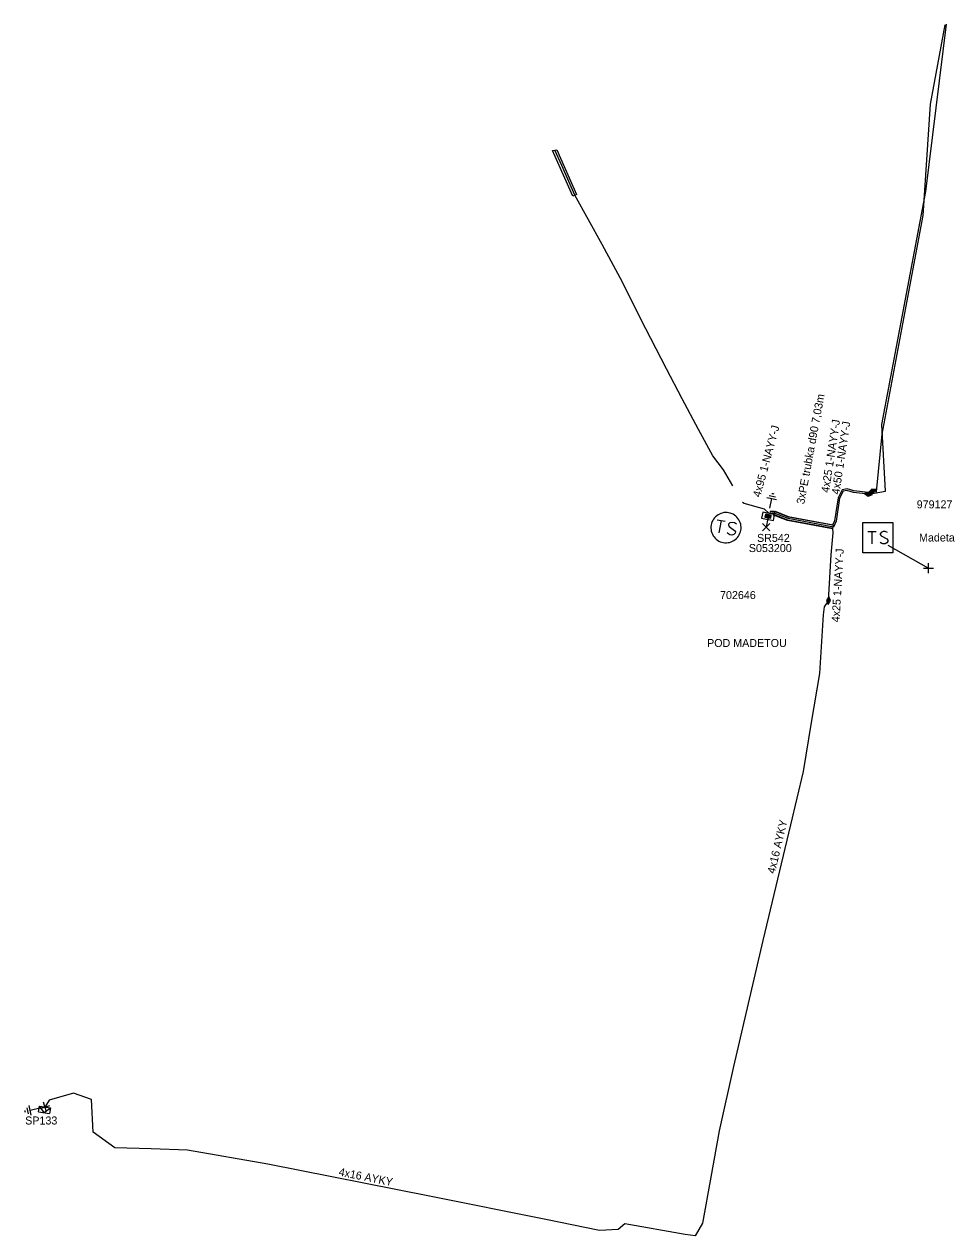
# Model space of a CAD drawing. Extents: x -737417 to -734469, y -1145580 to -1142703.
# Drawn here: x -734991.9 to -734875.7, y -1142926.1 to -1142774.8 of the extents above; entities that cross this region are included whole.
import ezdxf

# ---------------------------------------------------------------- set-up
doc = ezdxf.new("R2010")
doc.units = 0
for name, color, linetype in [('Vrstva 1', 7, 'Continuous'), ('Vrstva 14', 7, 'Continuous'), ('Vrstva 15', 7, 'Continuous'), ('Vrstva 19', 7, 'Continuous'), ('Vrstva 20', 7, 'Continuous'), ('Vrstva 21', 7, 'Continuous'), ('Vrstva 25', 7, 'Continuous'), ('Vrstva 26', 7, 'Continuous'), ('Vrstva 27', 7, 'Continuous'), ('Vrstva 28', 7, 'Continuous'), ('Vrstva 29', 7, 'Continuous'), ('Vrstva 30', 7, 'Continuous'), ('Vrstva 31', 7, 'Continuous'), ('Vrstva 33', 7, 'Continuous'), ('Vrstva 34', 7, 'Continuous'), ('Vrstva 4', 7, 'Continuous'), ('Vrstva 5', 7, 'Continuous'), ('Vrstva 52', 7, 'Continuous'), ('Vrstva 54', 7, 'Continuous'), ('Vrstva 59', 7, 'Continuous'), ('Vrstva 6', 7, 'Continuous'), ('Vrstva 8', 7, 'Continuous'), ('Vrstva 9', 7, 'Continuous')]:
    doc.layers.add(name, color=color, linetype=linetype)

# ---------------------------------------------------------------- blocks, each defined once
blk = doc.blocks.new('NN870')
at = {"layer": 'Vrstva 4'}
for points in [[(0, -0.25), (0.5, 0), (0, 0.25), (-0.5, 0), (0, -0.25)], [(0.37, 0), (0, 0.19), (-0.36, 0), (0, -0.19), (0.37, 0)], [(0.24, 0), (0, 0.12), (-0.25, 0), (0, -0.12), (0.24, 0)], [(0.12, 0), (0, 0.06), (-0.13, 0), (0, -0.06), (0.12, 0)]]:
    blk.add_lwpolyline(points, dxfattribs=at)
blk = doc.blocks.new('NN800')
at = {"layer": 'Vrstva 1'}
for points in [[(-0.44, 0.44), (0.44, -0.44)], [(-0.44, -0.44), (0.44, 0.44)]]:
    blk.add_lwpolyline(points, dxfattribs=at)
blk = doc.blocks.new('NN620')
at = {"layer": 'Vrstva 8'}
for points in [[(0.75, 0), (-0.75, 0)], [(-0.75, 0), (-0.75, -0.75)], [(0.75, -0.75), (0.75, 0)], [(-0.75, -0.75), (0.75, -0.75)], [(0.37, -0.18), (-0.38, -0.18)], [(-0.38, -0.18), (-0.38, -0.56)], [(-0.38, -0.56), (0.37, -0.56)], [(0.32, -0.23), (-0.33, -0.23)], [(-0.33, -0.23), (-0.33, -0.51)], [(-0.33, -0.51), (0.32, -0.51)], [(0.27, -0.27), (-0.28, -0.27)], [(-0.28, -0.27), (-0.28, -0.46)], [(-0.28, -0.46), (0.27, -0.46)], [(0.23, -0.32), (-0.23, -0.32)], [(-0.23, -0.32), (-0.23, -0.42)], [(-0.23, -0.42), (0.23, -0.42)], [(-0.19, -0.37), (0.19, -0.37)], [(0.23, -0.42), (0.23, -0.32)], [(0.27, -0.46), (0.27, -0.27)], [(0.32, -0.51), (0.32, -0.23)], [(0.37, -0.56), (0.37, -0.18)]]:
    blk.add_lwpolyline(points, dxfattribs=at)
blk = doc.blocks.new('NN630')
at = {"layer": 'Vrstva 9'}
for points in [[(0, -0.7), (-0.7, 0)], [(-0.7, -0.7), (-0.7, 0), (0.7, 0), (0.7, -0.7)], [(-0.7, -0.7), (0.7, -0.7)], [(0, -0.7), (0.7, 0)]]:
    blk.add_lwpolyline(points, dxfattribs=at)
blk = doc.blocks.new('NN810')
at = {"layer": 'Vrstva 14'}
for points in [[(0, -0.64), (0, -1.89)], [(0.63, -1.89), (-0.62, -1.89)], [(0.39, -2.2), (-0.4, -2.2)], [(0, -2.52), (-0.12, -2.52)], [(0.14, -2.52), (0, -2.52)]]:
    blk.add_lwpolyline(points, dxfattribs=at)
blk = doc.blocks.new('NN640')
at = {"layer": 'Vrstva 6'}
for points in [[(-1.89, 1.89), (1.89, 1.89)], [(-1.89, -1.89), (-1.89, 1.89)], [(1.89, 1.89), (1.89, -1.89)], [(-1.26, 0.79), (-0.22, 0.79)], [(-0.73, 0.79), (-0.73, -0.79)], [(1.2, 0.66), (0.94, 0.79), (0.66, 0.79), (0.41, 0.66), (0.28, 0.47), (0.28, 0.41), (0.41, 0.22), (1.13, -0.16), (1.26, -0.32), (1.26, -0.47), (1.13, -0.66), (0.91, -0.79), (0.63, -0.79), (0.5, -0.73), (0.28, -0.6)], [(1.89, -1.89), (-1.89, -1.89)]]:
    blk.add_lwpolyline(points, dxfattribs=at)
blk = doc.blocks.new('NN610')
at = {"layer": 'Vrstva 6'}
for points in [[(1.88, 0), (1.87, 0.2), (1.84, 0.39), (1.79, 0.58), (1.72, 0.77), (1.63, 0.94), (1.52, 1.11), (1.4, 1.26), (1.26, 1.4), (1.1, 1.53), (0.94, 1.63), (0.76, 1.72), (0.58, 1.8), (0.19, 1.88), (0.19, 1.88), (-0.01, 1.89), (-0.21, 1.88), (-0.4, 1.85), (-0.59, 1.8), (-0.78, 1.72), (-0.95, 1.63), (-1.12, 1.53), (-1.27, 1.4), (-1.41, 1.26), (-1.54, 1.11), (-1.64, 0.94), (-1.73, 0.77), (-1.8, 0.58), (-1.86, 0.39), (-1.89, 0.2), (-1.9, 0), (-1.89, -0.2), (-1.86, -0.39), (-1.8, -0.58), (-1.73, -0.77), (-1.64, -0.95), (-1.54, -1.11), (-1.41, -1.27), (-1.27, -1.41), (-1.12, -1.53), (-0.95, -1.64), (-0.78, -1.73), (-0.59, -1.8), (-0.4, -1.85), (-0.21, -1.88), (-0.01, -1.89), (0.19, -1.88), (0.39, -1.85), (0.58, -1.8), (0.76, -1.73), (0.94, -1.64), (1.1, -1.53), (1.26, -1.41), (1.4, -1.27), (1.52, -1.11), (1.63, -0.95), (1.72, -0.77), (1.79, -0.58), (1.84, -0.39), (1.87, -0.2), (1.88, 0)], [(-1.27, 0.78), (-0.26, 0.78)], [(-0.76, 0.78), (-0.76, -0.79)], [(1.19, 0.66), (0.94, 0.78), (0.62, 0.78), (0.37, 0.66), (0.24, 0.47), (0.24, 0.4), (0.37, 0.22), (1.12, -0.16), (1.25, -0.32), (1.25, -0.48), (1.12, -0.67), (0.87, -0.79), (0.62, -0.79), (0.49, -0.73), (0.24, -0.6)]]:
    blk.add_lwpolyline(points, dxfattribs=at)

msp = doc.modelspace()

# ---------------------------------------------------------------- linework, layer by layer
at = {"layer": 'Vrstva 20'}
for points in [[(-734925.42, -1142790.46), (-734922.94, -1142796.01), (-734923.4, -1142796.22), (-734925.93, -1142790.54)], [(-734890.87, -1142837.3), (-734890.96, -1142837.79), (-734896.57, -1142836.75), (-734898.32, -1142836.07), (-734898.14, -1142835.6), (-734896.48, -1142836.26)]]:
    msp.add_lwpolyline(points, close=True, dxfattribs=at)
at = {"layer": 'Vrstva 5'}
for points in [[(-734886.46, -1142833.45), (-734884.32, -1142833.09), (-734884.8, -1142824.75), (-734879.31, -1142795.66), (-734876.72, -1142774.76)], [(-734903.41, -1142832.41), (-734904.56, -1142830.41), (-734905.89, -1142828.67), (-734907.69, -1142825.4), (-734909.73, -1142821.55), (-734911.68, -1142817.81), (-734914.95, -1142811.51), (-734917.19, -1142806.98), (-734919.72, -1142802.29), (-734923.17, -1142796.11), (-734924.76, -1142792.42), (-734925.65, -1142790.49)], [(-734885.96, -1142833.06), (-734886.48, -1142833.25), (-734888.29, -1142833.07), (-734889.14, -1142832.82), (-734889.77, -1142832.91), (-734890.27, -1142833.91), (-734890.71, -1142836.79), (-734890.94, -1142837.34), (-734896.45, -1142836.32), (-734898.2, -1142835.63), (-734898.74, -1142835.65), (-734898.78, -1142835.89)], [(-734898.93, -1142835.86), (-734899.47, -1142835.33), (-734901.99, -1142834.65), (-734902.21, -1142834.5)], [(-734886.46, -1142833.45), (-734888.33, -1142833.27), (-734889.16, -1142833.02), (-734889.63, -1142833.09), (-734890.07, -1142833.97), (-734890.51, -1142836.85), (-734890.82, -1142837.57), (-734896.5, -1142836.51), (-734898.23, -1142835.83), (-734898.58, -1142835.84), (-734898.59, -1142835.92)], [(-734891.46, -1142846.75), (-734891.12, -1142841.05), (-734890.88, -1142838.31), (-734890.91, -1142837.76), (-734896.56, -1142836.7), (-734898.21, -1142836.05)]]:
    msp.add_lwpolyline(points, dxfattribs=at)
at = {"layer": 'Vrstva 52'}
for points in [[(-734885.96, -1142833.06), (-734885.46, -1142833.19), (-734884.76, -1142825.99), (-734883.75, -1142820.63), (-734879.64, -1142798.64), (-734878.72, -1142784.76), (-734876.9, -1142774.85)], [(-734891.46, -1142846.75), (-734892.02, -1142847.54), (-734892.14, -1142848.56), (-734892.6, -1142855.86), (-734893.61, -1142861.99), (-734894.62, -1142868.11), (-734896.21, -1142874.79), (-734899.67, -1142889.21), (-734903.32, -1142904.98), (-734905.1, -1142913.02), (-734906.16, -1142918.78), (-734907.21, -1142924.54), (-734908.12, -1142926.11), (-734909.38, -1142925.96), (-734916.91, -1142924.6), (-734917.72, -1142925.33), (-734920.09, -1142925.46), (-734926.79, -1142924.08), (-734941.29, -1142921.17), (-734961.49, -1142917.17), (-734971.56, -1142915.41), (-734976.1, -1142915.27), (-734980.64, -1142915.13), (-734983.33, -1142913.17), (-734983.52, -1142909.07), (-734985.79, -1142908.28), (-734988.84, -1142909.15), (-734989.35, -1142910.03)]]:
    msp.add_lwpolyline(points, dxfattribs=at)
at = {"layer": 'Vrstva 59'}
for points in [[(-734899.06, -1142836.51), (-734899.25, -1142837.59)], [(-734884.05, -1142839.82), (-734878.95, -1142842.72)]]:
    msp.add_lwpolyline(points, dxfattribs=at)

# ---------------------------------------------------------------- block references
at = {"layer": 'Vrstva 15'}
for p, rotation in [((-734898.93, -1142835.86), 168.26819729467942), ((-734989.35, -1142910.03), -77.21482219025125)]:
    msp.add_blockref('NN810', p, dxfattribs=dict(at, rotation=rotation))
at = {"layer": 'Vrstva 19'}
for p, rotation in [((-734885.96, -1142833.06), 20.337544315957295), ((-734886.46, -1142833.45), -5.583288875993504), ((-734891.46, -1142846.75), 86.58640281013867)]:
    msp.add_blockref('NN870', p, dxfattribs=dict(at, rotation=rotation))
at = {"layer": 'Vrstva 25', "rotation": -10.143019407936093}
msp.add_blockref('NN610', (-734904.26, -1142837.65), dxfattribs=at)
at = {"layer": 'Vrstva 25'}
msp.add_blockref('NN640', (-734885.3, -1142838.9), dxfattribs=at)
at = {"layer": 'Vrstva 28', "rotation": -11.454138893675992}
msp.add_blockref('NN620', (-734898.93, -1142835.86), dxfattribs=at)
at = {"layer": 'Vrstva 31', "rotation": -9.135105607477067}
msp.add_blockref('NN630', (-734989.35, -1142910.03), dxfattribs=at)
at = {"layer": 'Vrstva 34'}
msp.add_blockref('NN800', (-734899.25, -1142837.59), dxfattribs=at)
for p, rotation in [((-734878.95, -1142842.72), 44.99999995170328), ((-734989.35, -1142910.03), 63.62788614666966)]:
    msp.add_blockref('NN800', p, dxfattribs=dict(at, rotation=rotation))

# ---------------------------------------------------------------- texts
at = {"layer": 'Vrstva 21'}
msp.add_text('3xPE trubka d90 7,03m', height=1, rotation=79.447, dxfattribs=at).set_placement((-734894.5, -1142834.78))
at = {"layer": 'Vrstva 26'}
for s, p in [('979127', (-734880.44, -1142835.24)), ('702646', (-734905.01, -1142846.57))]:
    msp.add_text(s, height=1, dxfattribs=at).set_placement(p)
at = {"layer": 'Vrstva 27'}
for s, p in [('Madeta', (-734880.15, -1142839.38)), ('POD MADETOU', (-734906.63, -1142852.56))]:
    msp.add_text(s, height=1, dxfattribs=at).set_placement(p)
at = {"layer": 'Vrstva 29'}
msp.add_text('S053200', height=1, dxfattribs=at).set_placement((-734901.41, -1142840.7))
at = {"layer": 'Vrstva 30'}
msp.add_text('SR542', height=1, dxfattribs=at).set_placement((-734900.39, -1142839.43))
at = {"layer": 'Vrstva 33'}
msp.add_text('SP133', height=1, dxfattribs=at).set_placement((-734991.82, -1142912.21))
at = {"layer": 'Vrstva 54'}
for rotation, p in [(76.621, (-734898.17, -1142880.94)), (348.802, (-734952.71, -1142918.58))]:
    msp.add_text('4x16 AYKY', height=1, rotation=rotation, dxfattribs=at).set_placement(p)
at = {"layer": 'Vrstva 6'}
for s, rotation, p in [('4x95 1-NAYY-J', 74.899, (-734899.98, -1142833.92)), ('4x25 1-NAYY-J', 81.303, (-734891.4, -1142833.33)), ('4x50 1-NAYY-J', 81.324, (-734890.11, -1142833.56)), ('4x25 1-NAYY-J', 86.586, (-734890.09, -1142849.49))]:
    msp.add_text(s, height=1, rotation=rotation, dxfattribs=at).set_placement(p)

doc.saveas('drawing.dxf')
